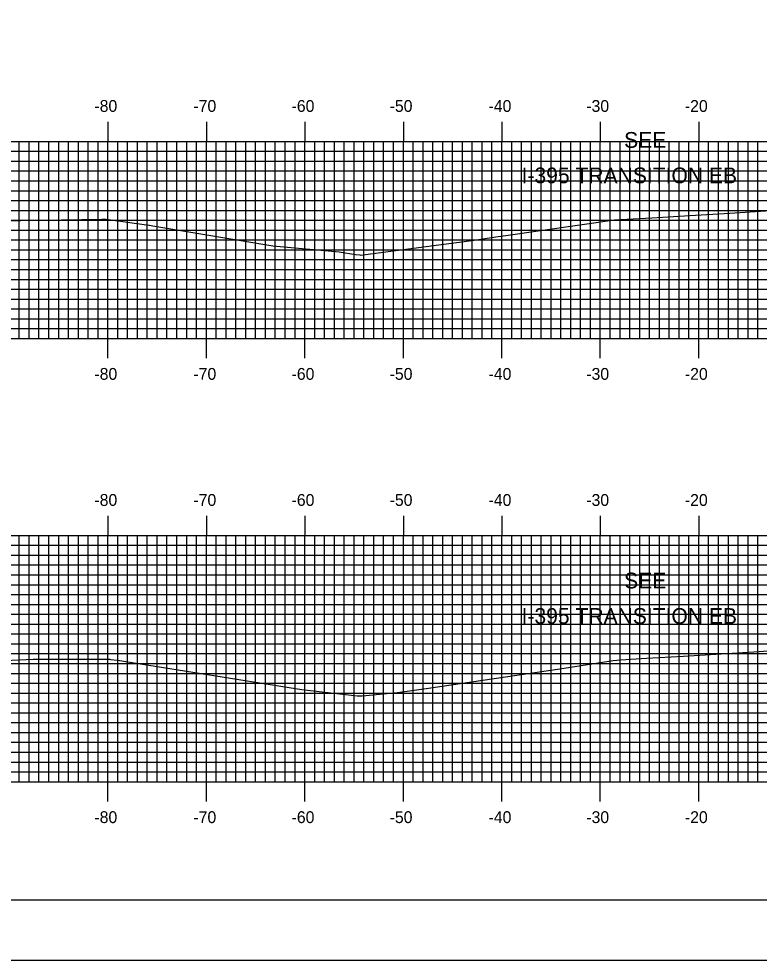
# Model space of a CAD drawing. Extents: x 842175 to 842518, y 363538 to 363758.
# Drawn here: x 842251.8 to 842327, y 363537.6 to 363633.2 of the extents above; entities that cross this region are included whole.
import ezdxf

# ---------------------------------------------------------------- set-up
doc = ezdxf.new("R2010")
doc.units = 0
for name, color, linetype in [('ANNOTATION', 7, 'Continuous'), ('BORDER', 7, 'Continuous'), ('H_V ANNOTATION', 7, 'Continuous'), ('MAJOR', 7, 'Continuous'), ('MINOR', 7, 'Continuous'), ('PLOT BOUNDARY', 7, 'Continuous'), ('S_Roadway_Centerline', 7, 'Continuous')]:
    doc.layers.add(name, color=color, linetype=linetype)

msp = doc.modelspace()

# ---------------------------------------------------------------- linework, layer by layer
at = {"layer": 'BORDER'}
msp.add_lwpolyline([(842191.285, 363543.721), (842511.285, 363543.721), (842511.285, 363753.721), (842191.285, 363753.721)], close=True, dxfattribs=at)
at = {"layer": 'MAJOR'}
for p, q in [((842260.885, 363622.725), (842260.885, 363620.721)), ((842270.885, 363622.725), (842270.885, 363620.721)), ((842280.885, 363622.725), (842280.885, 363620.721)), ((842290.885, 363622.725), (842290.885, 363620.721)), ((842300.885, 363622.725), (842300.885, 363620.721)), ((842310.885, 363622.725), (842310.885, 363620.721)), ((842320.885, 363622.725), (842320.885, 363620.721)), ((842200.885, 363620.721), (842480.885, 363620.721)), ((842200.885, 363620.721), (842480.885, 363620.721)), ((842260.885, 363600.721), (842260.885, 363620.721)), ((842270.885, 363600.721), (842270.885, 363620.721)), ((842280.885, 363600.721), (842280.885, 363620.721)), ((842290.885, 363600.721), (842290.885, 363620.721)), ((842300.885, 363600.721), (842300.885, 363620.721)), ((842310.885, 363600.721), (842310.885, 363620.721)), ((842320.885, 363600.721), (842320.885, 363620.721)), ((842200.885, 363615.721), (842480.885, 363615.721)), ((842200.885, 363610.721), (842480.885, 363610.721)), ((842200.885, 363605.721), (842480.885, 363605.721)), ((842200.885, 363600.721), (842480.885, 363600.721)), ((842200.885, 363600.721), (842480.885, 363600.721)), ((842260.885, 363598.717), (842260.885, 363600.721)), ((842270.885, 363598.717), (842270.885, 363600.721)), ((842280.885, 363598.717), (842280.885, 363600.721)), ((842290.885, 363598.717), (842290.885, 363600.721)), ((842300.885, 363598.717), (842300.885, 363600.721)), ((842310.885, 363598.717), (842310.885, 363600.721)), ((842320.885, 363598.717), (842320.885, 363600.721)), ((842260.885, 363582.725), (842260.885, 363580.721)), ((842270.885, 363582.725), (842270.885, 363580.721)), ((842280.885, 363582.725), (842280.885, 363580.721)), ((842290.885, 363582.725), (842290.885, 363580.721)), ((842300.885, 363582.725), (842300.885, 363580.721)), ((842310.885, 363582.725), (842310.885, 363580.721)), ((842320.885, 363582.725), (842320.885, 363580.721)), ((842200.885, 363580.721), (842480.885, 363580.721)), ((842200.885, 363580.721), (842480.885, 363580.721)), ((842260.885, 363555.721), (842260.885, 363580.721)), ((842270.885, 363555.721), (842270.885, 363580.721)), ((842280.885, 363555.721), (842280.885, 363580.721)), ((842290.885, 363555.721), (842290.885, 363580.721)), ((842300.885, 363555.721), (842300.885, 363580.721)), ((842310.885, 363555.721), (842310.885, 363580.721)), ((842320.885, 363555.721), (842320.885, 363580.721)), ((842200.885, 363575.721), (842480.885, 363575.721)), ((842200.885, 363570.721), (842480.885, 363570.721)), ((842200.885, 363565.721), (842480.885, 363565.721)), ((842200.885, 363560.721), (842480.885, 363560.721)), ((842200.885, 363555.721), (842480.885, 363555.721)), ((842200.885, 363555.721), (842480.885, 363555.721)), ((842260.885, 363553.717), (842260.885, 363555.721)), ((842270.885, 363553.717), (842270.885, 363555.721)), ((842280.885, 363553.717), (842280.885, 363555.721)), ((842290.885, 363553.717), (842290.885, 363555.721)), ((842300.885, 363553.717), (842300.885, 363555.721)), ((842310.885, 363553.717), (842310.885, 363555.721)), ((842320.885, 363553.717), (842320.885, 363555.721))]:
    msp.add_line(p, q, dxfattribs=at)
at = {"layer": 'MINOR'}
for p, q in [((842251.885, 363600.721), (842251.885, 363620.721)), ((842252.885, 363600.721), (842252.885, 363620.721)), ((842253.885, 363600.721), (842253.885, 363620.721)), ((842254.885, 363600.721), (842254.885, 363620.721)), ((842255.885, 363600.721), (842255.885, 363620.721)), ((842256.885, 363600.721), (842256.885, 363620.721)), ((842257.885, 363600.721), (842257.885, 363620.721)), ((842258.885, 363600.721), (842258.885, 363620.721)), ((842259.885, 363600.721), (842259.885, 363620.721)), ((842261.885, 363600.721), (842261.885, 363620.721)), ((842262.885, 363600.721), (842262.885, 363620.721)), ((842263.885, 363600.721), (842263.885, 363620.721)), ((842264.885, 363600.721), (842264.885, 363620.721)), ((842265.885, 363600.721), (842265.885, 363620.721)), ((842266.885, 363600.721), (842266.885, 363620.721)), ((842267.885, 363600.721), (842267.885, 363620.721)), ((842268.885, 363600.721), (842268.885, 363620.721)), ((842269.885, 363600.721), (842269.885, 363620.721)), ((842271.885, 363600.721), (842271.885, 363620.721)), ((842272.885, 363600.721), (842272.885, 363620.721)), ((842273.885, 363600.721), (842273.885, 363620.721)), ((842274.885, 363600.721), (842274.885, 363620.721)), ((842275.885, 363600.721), (842275.885, 363620.721)), ((842276.885, 363600.721), (842276.885, 363620.721)), ((842277.885, 363600.721), (842277.885, 363620.721)), ((842278.885, 363600.721), (842278.885, 363620.721)), ((842279.885, 363600.721), (842279.885, 363620.721)), ((842281.885, 363600.721), (842281.885, 363620.721)), ((842282.885, 363600.721), (842282.885, 363620.721)), ((842283.885, 363600.721), (842283.885, 363620.721)), ((842284.885, 363600.721), (842284.885, 363620.721)), ((842285.885, 363600.721), (842285.885, 363620.721)), ((842286.885, 363600.721), (842286.885, 363620.721)), ((842287.885, 363600.721), (842287.885, 363620.721)), ((842288.885, 363600.721), (842288.885, 363620.721)), ((842289.885, 363600.721), (842289.885, 363620.721)), ((842291.885, 363600.721), (842291.885, 363620.721)), ((842292.885, 363600.721), (842292.885, 363620.721)), ((842293.885, 363600.721), (842293.885, 363620.721)), ((842294.885, 363600.721), (842294.885, 363620.721)), ((842295.885, 363600.721), (842295.885, 363620.721)), ((842296.885, 363600.721), (842296.885, 363620.721)), ((842297.885, 363600.721), (842297.885, 363620.721)), ((842298.885, 363600.721), (842298.885, 363620.721)), ((842299.885, 363600.721), (842299.885, 363620.721)), ((842301.885, 363600.721), (842301.885, 363620.721)), ((842302.885, 363600.721), (842302.885, 363620.721)), ((842303.885, 363600.721), (842303.885, 363620.721)), ((842304.885, 363600.721), (842304.885, 363620.721)), ((842305.885, 363600.721), (842305.885, 363620.721)), ((842306.885, 363600.721), (842306.885, 363620.721)), ((842307.885, 363600.721), (842307.885, 363620.721)), ((842308.885, 363600.721), (842308.885, 363620.721)), ((842309.885, 363600.721), (842309.885, 363620.721)), ((842311.885, 363600.721), (842311.885, 363620.721)), ((842312.885, 363600.721), (842312.885, 363620.721)), ((842313.885, 363600.721), (842313.885, 363620.721)), ((842314.885, 363600.721), (842314.885, 363620.721)), ((842315.885, 363600.721), (842315.885, 363620.721)), ((842316.885, 363600.721), (842316.885, 363620.721)), ((842317.885, 363600.721), (842317.885, 363620.721)), ((842318.885, 363600.721), (842318.885, 363620.721)), ((842319.885, 363600.721), (842319.885, 363620.721)), ((842321.885, 363600.721), (842321.885, 363620.721)), ((842322.885, 363600.721), (842322.885, 363620.721)), ((842323.885, 363600.721), (842323.885, 363620.721)), ((842324.885, 363600.721), (842324.885, 363620.721)), ((842325.885, 363600.721), (842325.885, 363620.721)), ((842326.885, 363600.721), (842326.885, 363620.721)), ((842200.885, 363619.721), (842480.885, 363619.721)), ((842200.885, 363618.721), (842480.885, 363618.721)), ((842200.885, 363617.721), (842480.885, 363617.721)), ((842200.885, 363616.721), (842480.885, 363616.721)), ((842200.885, 363614.721), (842480.885, 363614.721)), ((842200.885, 363613.721), (842480.885, 363613.721)), ((842200.885, 363612.721), (842480.885, 363612.721)), ((842200.885, 363611.721), (842480.885, 363611.721)), ((842200.885, 363609.721), (842480.885, 363609.721)), ((842200.885, 363608.721), (842480.885, 363608.721)), ((842200.885, 363607.721), (842480.885, 363607.721)), ((842200.885, 363606.721), (842480.885, 363606.721)), ((842200.885, 363604.721), (842480.885, 363604.721)), ((842200.885, 363603.721), (842480.885, 363603.721)), ((842200.885, 363602.721), (842480.885, 363602.721)), ((842200.885, 363601.721), (842480.885, 363601.721)), ((842251.885, 363555.721), (842251.885, 363580.721)), ((842252.885, 363555.721), (842252.885, 363580.721)), ((842253.885, 363555.721), (842253.885, 363580.721)), ((842254.885, 363555.721), (842254.885, 363580.721)), ((842255.885, 363555.721), (842255.885, 363580.721)), ((842256.885, 363555.721), (842256.885, 363580.721)), ((842257.885, 363555.721), (842257.885, 363580.721)), ((842258.885, 363555.721), (842258.885, 363580.721)), ((842259.885, 363555.721), (842259.885, 363580.721)), ((842261.885, 363555.721), (842261.885, 363580.721)), ((842262.885, 363555.721), (842262.885, 363580.721)), ((842263.885, 363555.721), (842263.885, 363580.721)), ((842264.885, 363555.721), (842264.885, 363580.721)), ((842265.885, 363555.721), (842265.885, 363580.721)), ((842266.885, 363555.721), (842266.885, 363580.721)), ((842267.885, 363555.721), (842267.885, 363580.721)), ((842268.885, 363555.721), (842268.885, 363580.721)), ((842269.885, 363555.721), (842269.885, 363580.721)), ((842271.885, 363555.721), (842271.885, 363580.721)), ((842272.885, 363555.721), (842272.885, 363580.721)), ((842273.885, 363555.721), (842273.885, 363580.721)), ((842274.885, 363555.721), (842274.885, 363580.721)), ((842275.885, 363555.721), (842275.885, 363580.721)), ((842276.885, 363555.721), (842276.885, 363580.721)), ((842277.885, 363555.721), (842277.885, 363580.721)), ((842278.885, 363555.721), (842278.885, 363580.721)), ((842279.885, 363555.721), (842279.885, 363580.721)), ((842281.885, 363555.721), (842281.885, 363580.721)), ((842282.885, 363555.721), (842282.885, 363580.721)), ((842283.885, 363555.721), (842283.885, 363580.721)), ((842284.885, 363555.721), (842284.885, 363580.721)), ((842285.885, 363555.721), (842285.885, 363580.721)), ((842286.885, 363555.721), (842286.885, 363580.721)), ((842287.885, 363555.721), (842287.885, 363580.721)), ((842288.885, 363555.721), (842288.885, 363580.721)), ((842289.885, 363555.721), (842289.885, 363580.721)), ((842291.885, 363555.721), (842291.885, 363580.721)), ((842292.885, 363555.721), (842292.885, 363580.721)), ((842293.885, 363555.721), (842293.885, 363580.721)), ((842294.885, 363555.721), (842294.885, 363580.721)), ((842295.885, 363555.721), (842295.885, 363580.721)), ((842296.885, 363555.721), (842296.885, 363580.721)), ((842297.885, 363555.721), (842297.885, 363580.721)), ((842298.885, 363555.721), (842298.885, 363580.721)), ((842299.885, 363555.721), (842299.885, 363580.721)), ((842301.885, 363555.721), (842301.885, 363580.721)), ((842302.885, 363555.721), (842302.885, 363580.721)), ((842303.885, 363555.721), (842303.885, 363580.721)), ((842304.885, 363555.721), (842304.885, 363580.721)), ((842305.885, 363555.721), (842305.885, 363580.721)), ((842306.885, 363555.721), (842306.885, 363580.721)), ((842307.885, 363555.721), (842307.885, 363580.721)), ((842308.885, 363555.721), (842308.885, 363580.721)), ((842309.885, 363555.721), (842309.885, 363580.721)), ((842311.885, 363555.721), (842311.885, 363580.721)), ((842312.885, 363555.721), (842312.885, 363580.721)), ((842313.885, 363555.721), (842313.885, 363580.721)), ((842314.885, 363555.721), (842314.885, 363580.721)), ((842315.885, 363555.721), (842315.885, 363580.721)), ((842316.885, 363555.721), (842316.885, 363580.721)), ((842317.885, 363555.721), (842317.885, 363580.721)), ((842318.885, 363555.721), (842318.885, 363580.721)), ((842319.885, 363555.721), (842319.885, 363580.721)), ((842321.885, 363555.721), (842321.885, 363580.721)), ((842322.885, 363555.721), (842322.885, 363580.721)), ((842323.885, 363555.721), (842323.885, 363580.721)), ((842324.885, 363555.721), (842324.885, 363580.721)), ((842325.885, 363555.721), (842325.885, 363580.721)), ((842326.885, 363555.721), (842326.885, 363580.721)), ((842200.885, 363579.721), (842480.885, 363579.721)), ((842200.885, 363578.721), (842480.885, 363578.721)), ((842200.885, 363577.721), (842480.885, 363577.721)), ((842200.885, 363576.721), (842480.885, 363576.721)), ((842200.885, 363574.721), (842480.885, 363574.721)), ((842200.885, 363573.721), (842480.885, 363573.721)), ((842200.885, 363572.721), (842480.885, 363572.721)), ((842200.885, 363571.721), (842480.885, 363571.721)), ((842200.885, 363569.721), (842480.885, 363569.721)), ((842200.885, 363568.721), (842480.885, 363568.721)), ((842200.885, 363567.721), (842480.885, 363567.721)), ((842200.885, 363566.721), (842480.885, 363566.721)), ((842200.885, 363564.721), (842480.885, 363564.721)), ((842200.885, 363563.721), (842480.885, 363563.721)), ((842200.885, 363562.721), (842480.885, 363562.721)), ((842200.885, 363561.721), (842480.885, 363561.721)), ((842200.885, 363559.721), (842480.885, 363559.721)), ((842200.885, 363558.721), (842480.885, 363558.721)), ((842200.885, 363557.721), (842480.885, 363557.721)), ((842200.885, 363556.721), (842480.885, 363556.721))]:
    msp.add_line(p, q, dxfattribs=at)
at = {"layer": 'PLOT BOUNDARY'}
msp.add_lwpolyline([(842175.098, 363537.603), (842515.098, 363537.603), (842515.098, 363757.603), (842175.098, 363757.603)], close=True, dxfattribs=at)
at = {"layer": 'S_Roadway_Centerline'}
for points in [[(842248.006, 363612.543), (842252.059, 363612.702), (842260.267, 363612.832), (842260.71, 363612.826), (842265.027, 363612.223), (842265.121, 363612.209), (842265.431, 363612.155), (842277.632, 363610.107), (842284.374, 363609.504), (842286.035, 363609.237), (842286.454, 363609.219), (842286.536, 363609.189), (842298.071, 363610.708), (842300.522, 363611.058), (842301.291, 363611.175), (842312.323, 363612.748), (842316.121, 363612.954), (842319.991, 363613.189), (842324.041, 363613.441), (842328.696, 363613.749)], [(842246.018, 363567.829), (842253.285, 363568.157), (842260.008, 363568.175), (842261.084, 363568.15), (842261.165, 363568.139), (842261.857, 363568.043), (842277.145, 363565.639), (842280.588, 363565.076), (842286.205, 363564.453), (842286.69, 363564.443), (842290.276, 363564.762), (842293.432, 363565.229), (842306.768, 363567.17), (842312.198, 363568.017), (842312.92, 363568.1), (842315.581, 363568.258), (842319.319, 363568.456), (842327.004, 363568.95), (842328.764, 363569.069)]]:
    msp.add_lwpolyline(points, dxfattribs=at)

# ---------------------------------------------------------------- texts
at = {"layer": 'ANNOTATION'}
for s, p in [('SEE', (842313.302, 363620.073)), ('I-395 TRANSITION EB', (842302.889, 363616.473)), ('SEE', (842313.302, 363575.344)), ('I-395 TRANSITION EB', (842302.889, 363571.744))]:
    msp.add_text(s, height=1.6, dxfattribs=at).set_placement(p)
at = {"layer": 'H_V ANNOTATION'}
for s, p in [('-80', (842259.515, 363623.721)), ('-70', (842269.568, 363623.721)), ('-60', (842279.536, 363623.721)), ('-50', (842289.493, 363623.721)), ('-40', (842299.536, 363623.721)), ('-30', (842309.461, 363623.721)), ('-20', (842319.472, 363623.721)), ('-80', (842259.515, 363596.521)), ('-70', (842269.568, 363596.521)), ('-60', (842279.536, 363596.521)), ('-50', (842289.493, 363596.521)), ('-40', (842299.536, 363596.521)), ('-30', (842309.461, 363596.521)), ('-20', (842319.472, 363596.521)), ('-80', (842259.515, 363583.721)), ('-70', (842269.568, 363583.721)), ('-60', (842279.536, 363583.721)), ('-50', (842289.493, 363583.721)), ('-40', (842299.536, 363583.721)), ('-30', (842309.461, 363583.721)), ('-20', (842319.472, 363583.721)), ('-80', (842259.515, 363551.521)), ('-70', (842269.568, 363551.521)), ('-60', (842279.536, 363551.521)), ('-50', (842289.493, 363551.521)), ('-40', (842299.536, 363551.521)), ('-30', (842309.461, 363551.521)), ('-20', (842319.472, 363551.521))]:
    msp.add_text(s, height=1.2, dxfattribs=at).set_placement(p)

doc.saveas('drawing.dxf')
